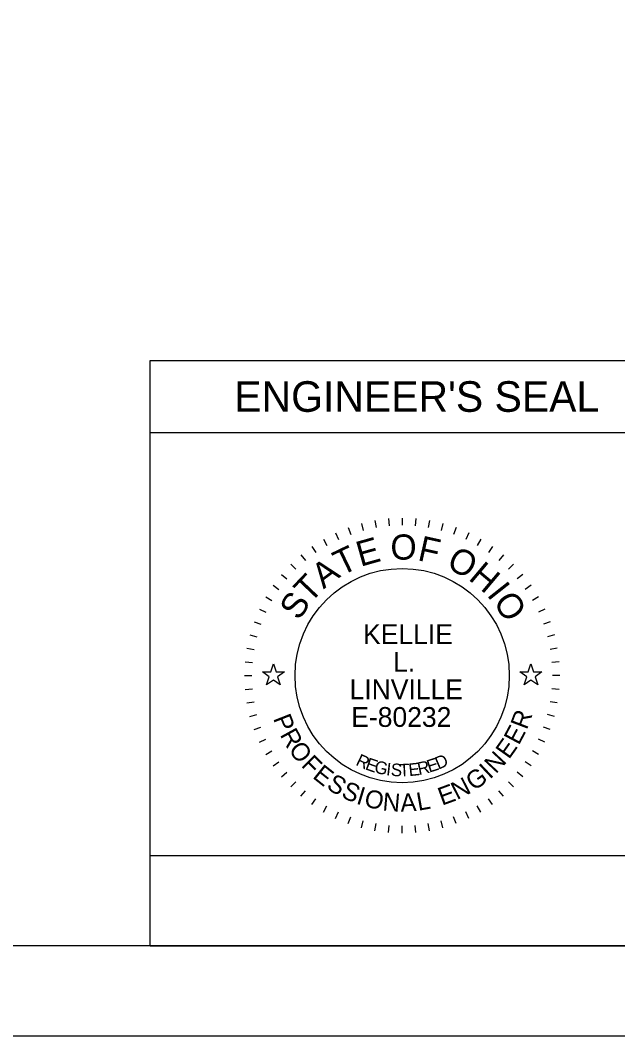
# Model space of a CAD drawing. Extents: x 0 to 34, y -2 to 22.
# Drawn here: x 6.63 to 9.95, y 0 to 5.64 of the extents above; entities that cross this region are included whole.
import ezdxf

# ---------------------------------------------------------------- set-up
doc = ezdxf.new("R2010")
doc.units = 0
for name, color, linetype in [('SH_Border', 7, 'Continuous'), ('SH_Cut_Line', 7, 'Continuous'), ('SH_Data', 7, 'Continuous'), ('SH_Seal', 7, 'Continuous')]:
    doc.layers.add(name, color=color, linetype=linetype)

msp = doc.modelspace()

# ---------------------------------------------------------------- linework, layer by layer
at = {"layer": 'SH_Border'}
msp.add_lwpolyline([(1.5, 21.5), (33.5, 21.5), (33.5, 0.5), (1.5, 0.5)], close=True, dxfattribs=at)
at = {"layer": 'SH_Cut_Line'}
msp.add_lwpolyline([(0, 0), (34, 0), (34, 22), (0, 22)], close=True, dxfattribs=at)
at = {"layer": 'SH_Data'}
for p, q in [((7.35, 0.5), (7.35, 3.75)), ((7.35, 3.75), (10.15, 3.75)), ((7.35, 3.35), (10.15, 3.35)), ((7.35, 0.5), (10.15, 0.5))]:
    msp.add_line(p, q, dxfattribs=at)
msp.add_lwpolyline([(7.35, 0.5), (7.35, 1), (10.15, 1), (10.15, 0.5)], close=True, dxfattribs=at)
at = {"layer": 'SH_Seal'}
for p, q in [((8.4507, 2.8222), (8.4644, 2.7846)), ((8.5235, 2.8452), (8.5339, 2.8065)), ((8.5981, 2.8617), (8.605, 2.8223)), ((8.6737, 2.8717), (8.6772, 2.8318)), ((8.75, 2.875), (8.75, 2.835)), ((8.8263, 2.8717), (8.8228, 2.8318)), ((8.9019, 2.8617), (8.895, 2.8223)), ((8.9765, 2.8452), (8.9661, 2.8065)), ((9.0493, 2.8222), (9.0356, 2.7846)), ((8.3802, 2.793), (8.3971, 2.7568)), ((9.1198, 2.793), (9.1029, 2.7568)), ((8.2481, 2.7168), (8.2711, 2.684)), ((8.3125, 2.7578), (8.3325, 2.7231)), ((9.1875, 2.7578), (9.1675, 2.7231)), ((9.2519, 2.7168), (9.2289, 2.684)), ((8.1876, 2.6703), (8.2133, 2.6396)), ((9.3124, 2.6703), (9.2867, 2.6396)), ((8.1313, 2.6187), (8.1596, 2.5904)), ((9.3687, 2.6187), (9.3404, 2.5904)), ((8.0797, 2.5624), (8.1104, 2.5367)), ((9.4203, 2.5624), (9.3896, 2.5367)), ((8.0332, 2.5019), (8.066, 2.4789)), ((9.4668, 2.5019), (9.434, 2.4789)), ((7.9922, 2.4375), (8.0269, 2.4175)), ((9.5078, 2.4375), (9.4731, 2.4175)), ((7.957, 2.3698), (7.9932, 2.3529)), ((9.543, 2.3698), (9.5068, 2.3529)), ((7.9278, 2.2993), (7.9654, 2.2856)), ((9.5722, 2.2993), (9.5346, 2.2856)), ((7.9048, 2.2265), (7.9435, 2.2161)), ((9.5952, 2.2265), (9.5565, 2.2161)), ((7.8883, 2.1519), (7.9277, 2.145)), ((9.6117, 2.1519), (9.5723, 2.145)), ((7.8783, 2.0763), (7.9182, 2.0728)), ((9.6217, 2.0763), (9.5818, 2.0728)), ((7.875, 2), (7.915, 2)), ((9.625, 2), (9.585, 2)), ((7.8783, 1.9237), (7.9182, 1.9272)), ((9.6217, 1.9237), (9.5818, 1.9272)), ((7.8883, 1.8481), (7.9277, 1.855)), ((9.6117, 1.8481), (9.5723, 1.855)), ((7.9048, 1.7735), (7.9435, 1.7839)), ((9.5952, 1.7735), (9.5565, 1.7839)), ((7.9278, 1.7007), (7.9654, 1.7144)), ((9.5722, 1.7007), (9.5346, 1.7144)), ((7.957, 1.6302), (7.9932, 1.6471)), ((9.543, 1.6302), (9.5068, 1.6471)), ((7.9922, 1.5625), (8.0269, 1.5825)), ((9.5078, 1.5625), (9.4731, 1.5825)), ((8.0332, 1.4981), (8.066, 1.5211)), ((9.4668, 1.4981), (9.434, 1.5211)), ((8.0797, 1.4376), (8.1104, 1.4633)), ((9.4203, 1.4376), (9.3896, 1.4633)), ((8.1313, 1.3813), (8.1596, 1.4096)), ((8.1876, 1.3297), (8.2133, 1.3604)), ((9.3124, 1.3297), (9.2867, 1.3604)), ((9.3687, 1.3813), (9.3404, 1.4096)), ((8.2481, 1.2832), (8.2711, 1.316)), ((9.2519, 1.2832), (9.2289, 1.316)), ((8.3125, 1.2422), (8.3325, 1.2769)), ((8.3802, 1.207), (8.3971, 1.2432)), ((9.1198, 1.207), (9.1029, 1.2432)), ((9.1875, 1.2422), (9.1675, 1.2769)), ((8.4507, 1.1778), (8.4644, 1.2154)), ((8.5235, 1.1548), (8.5339, 1.1935)), ((8.9765, 1.1548), (8.9661, 1.1935)), ((9.0493, 1.1778), (9.0356, 1.2154)), ((8.5981, 1.1383), (8.605, 1.1777)), ((8.6737, 1.1283), (8.6772, 1.1682)), ((8.75, 1.125), (8.75, 1.165)), ((8.8263, 1.1283), (8.8228, 1.1682)), ((8.9019, 1.1383), (8.895, 1.1777))]:
    msp.add_line(p, q, dxfattribs=at)
for points in [[(7.9736, 2.02), (8.0205, 2.02), (8.035, 2.0645), (8.0495, 2.02), (8.0964, 2.02), (8.0585, 1.9924), (8.073, 1.9478), (8.035, 1.9754), (7.997, 1.9478), (8.0115, 1.9924)], [(9.4036, 2.02), (9.4505, 2.02), (9.465, 2.0645), (9.4795, 2.02), (9.5264, 2.02), (9.4885, 1.9924), (9.503, 1.9478), (9.465, 1.9754), (9.427, 1.9478), (9.4415, 1.9924)]]:
    msp.add_lwpolyline(points, close=True, dxfattribs=at)
msp.add_circle((8.75, 2), 0.595, dxfattribs=at)

# ---------------------------------------------------------------- texts
at = {"layer": 'SH_Data'}
msp.add_text("ENGINEER'S SEAL", height=0.17, dxfattribs=at).set_placement((7.8176, 3.465))
at = {"layer": 'SH_Seal'}
for s, height, rotation, p in [('E', 0.14, 15.7571, (8.5184, 2.6038)), ('O', 0.14, 359.7812, (8.6847, 2.6443)), ('F', 0.14, 347.4362, (8.8311, 2.6417)), ('T', 0.14, 25.7167, (8.4116, 2.5518)), ('O', 0.14, 332.2586, (8.9898, 2.6015)), ('A', 0.14, 36.4747, (8.3134, 2.4781)), ('H', 0.14, 319.9136, (9.1132, 2.5361)), ('T', 0.14, 46.4344, (8.2383, 2.3964)), ('I', 0.14, 308.367, (9.2165, 2.4483)), ('S', 0.14, 57.1924, (8.1781, 2.3014)), ('O', 0.14, 303.1491, (9.2521, 2.4089)), ('R', 0.1, 69.2322, (9.4419, 1.6954)), ('P', 0.1, 291.494, (8.0323, 1.7621)), ('R', 0.1, 298.7311, (8.069, 1.6717)), ('E', 0.1, 61.9951, (9.3976, 1.6098)), ('E', 0.1, 54.758, (9.3433, 1.5314)), ('O', 0.1, 306.4666, (8.1155, 1.5883)), ('N', 0.1, 47.0224, (9.2702, 1.4508)), ('F', 0.1, 314.7068, (8.1843, 1.4983)), ('R', 0.07, 334.487, (8.4875, 1.5051)), ('E', 0.07, 341.04, (8.5406, 1.4801)), ('G', 0.07, 347.4752, (8.5914, 1.4618)), ('R', 0.07, 11.9184, (8.8425, 1.4474)), ('E', 0.07, 17.6836, (8.8998, 1.4602)), ('D', 0.07, 23.3052, (8.951, 1.477)), ('E', 0.1, 321.4393, (8.2478, 1.4348)), ('I', 0.07, 353.7858, (8.6591, 1.4468)), ('S', 0.07, 356.8926, (8.6858, 1.4429)), ('T', 0.07, 3.0061, (8.7357, 1.4387)), ('E', 0.07, 6.0117, (8.7889, 1.4412)), ('G', 0.1, 35.0469, (9.1481, 1.357)), ('I', 0.1, 43.287, (9.2368, 1.4214)), ('S', 0.1, 328.6764, (8.3243, 1.3752)), ('N', 0.1, 27.3113, (9.0545, 1.3075)), ('S', 0.1, 335.9134, (8.4064, 1.3266)), ('I', 0.1, 343.1505, (8.4906, 1.2897)), ('O', 0.1, 346.8859, (8.5339, 1.2751)), ('E', 0.1, 20.0742, (8.9712, 1.277)), ('N', 0.1, 355.1261, (8.6388, 1.2517)), ('A', 0.1, 2.8617, (8.7423, 1.2437)), ('L', 0.1, 10.0987, (8.8394, 1.249))]:
    msp.add_text(s, height=height, rotation=rotation, dxfattribs=at).set_placement(p)
for s, p in [('KELLIE', (8.5328, 2.1749)), ('L.', (8.6995, 2.0216)), ('LINVILLE', (8.458, 1.8684)), ('E-80232', (8.4672, 1.7151))]:
    msp.add_text(s, height=0.11, dxfattribs=at).set_placement(p)

doc.saveas('drawing.dxf')
